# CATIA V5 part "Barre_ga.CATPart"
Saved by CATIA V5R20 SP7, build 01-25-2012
Part number: Barre_ga
Bounding box of the stored display mesh (mm): x -40 to 20, y -114.479 to 107.15, z -40 to 179.5
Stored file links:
  G:\bon\Nouveau dossier\Barre_ga.CATPart
  G:\bon\Nouveau dossier\cgirerd.CATProduct
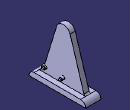
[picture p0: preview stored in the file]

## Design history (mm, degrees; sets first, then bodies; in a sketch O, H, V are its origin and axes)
Set1
  Point1 "H": linked copy from another document
  Point2 "symG": linked copy from another document
  Point3 "G": linked copy from another document
  Point4 "A": linked copy from another document
Body1 (main body)
  Sketch1 on yz-plane, origin (0, 0, 0), H (0, 1, 0), V (0, 0, 1)
    arc A1 centre (0, 152) radius 27.5 from (26.2652, 160.1479) to (-26.2652, 160.1479) ccw
    point P1 (0, 152)
    reference projected point E1 (0, 152) from Point1
    line L1 (26.2652, 160.1479) -> (82.1501, -20)
    reference projected point E2 (70.7107, 0) from Point2
    line L2 (-26.2652, 160.1479) -> (-71.9308, 12.9424)
    reference projected point E3 (-70.7107, 0) from Point3
    point P4 (82.1501, -20)
    line L3 (-82.1719, 3.5554) -> (-89.4792, -20)
    point P6 (-89.4792, -20)
    point P7 (-114.4792, -20)
    line L4 (-114.4792, -20) -> (-89.4792, -20)
    line L5 (107.1501, -20) -> (107.1501, -40)
    line L6 (107.1501, -40) -> (-114.4792, -40)
    line L7 (-114.4792, -40) -> (-114.4792, -20)
    point P8 (107.1501, -20)
    line L8 (82.1501, -20) -> (107.1501, -20)
    reference projected point E4 (-70.7107, 0) from Point3
    reference projected point E5 (0, 0) from Point4
    arc A2 centre (-70.7107, 0) radius 12 from (-72.2541, 11.9003) to (-82.1719, 3.5554) ccw
    point P11 (-70.7107, 0)
    reference projected point E6 (-70.7107, 0) from Point3
    line L9 (-71.9308, 12.9424) -> (-72.2541, 11.9003)
    radius A1 = 27.5
    distance L1 E2 = 5
    distance E3 L2 = 5
    length L5 = 20
    distance P8 P4 = 25
    distance P6 P7 = 25
    distance E4 L3 = 12
    distance L6 E5 = 40
    radius A2 = 12
    coincidence: E1 P1, L4 L8, P11 E6
    tangency: L1 A1, L2 A1
    horizontal: L4 H, L6 H, L8 H
    vertical: L5 V, L7 V
    parallelism: L3 L2, L9 L2
  Pad1: profile Sketch1, direction (-1, 0, 0), length 20
  Sketch2 on start face of Pad1, origin (0, 0, 0), H (0, 1, 0), V (0, 0, 1)
    point P1 (-114.4792, -20)
    line L1 (-114.4792, -20) -> (107.1501, -20)
    line L2 (107.1501, -20) -> (107.1501, -40)
    line L3 (107.1501, -40) -> (-114.4792, -40)
    line L4 (-114.4792, -40) -> (-114.4792, -20)
    point P2 (107.1501, -20)
    reference projected point E1 (-114.4792, -20) from vertex [face of Pad1 from Sketch1.L7 | start face of Pad1 | face of Pad1 from Sketch1.L4]
    reference projected point E2 (107.1501, -20) from vertex [face of Pad1 from Sketch1.L8 | start face of Pad1 | face of Pad1 from Sketch1.L5]
    length L4 = 20
    horizontal: L1 H, L3 H
    vertical: L2 V, L4 V
    coincidence: P1 E1, P2 E2
  Pad2: profile Sketch2, direction (1, 0, 0), length 20
  Sketch3 on end face of Pad1, origin (-20, 0, 0), H (0, -1, 0), V (0, 0, 1)
    point P1 (-107.1501, -20)
    line L1 (-107.1501, -20) -> (114.4792, -20)
    line L2 (114.4792, -20) -> (114.4792, -40)
    line L3 (114.4792, -40) -> (-107.1501, -40)
    line L4 (-107.1501, -40) -> (-107.1501, -20)
    point P2 (114.4792, -20)
    reference projected point E1 (-107.1501, -20) from vertex [face of Pad2 | end face of Pad1 | face of Pad2]
    reference projected point E2 (114.4792, -20) from vertex [face of Pad2 | end face of Pad1 | face of Pad2]
    length L2 = 20
    horizontal: L1 H, L3 H
    vertical: L2 V, L4 V
    coincidence: E1 P1, P2 E2
  Pad3: profile Sketch3, direction (-1, 0, 0), length 20
  Sketch4 on start face of Pad1, origin (0, 0, 0), H (0, 1, 0), V (0, 0, 1)
    circle A1 centre (-70.7107, 0) radius 6
    point P1 (-70.7107, 0)
    reference projected point E1 (-70.7107, 0) from Point3
    radius A1 = 6
    coincidence: P1 E1
  Pad4: profile Sketch4, direction (1, 0, 0), length 5
  Sketch5 on end face of Pad4, origin (5, 0, 0), H (0, 1, 0), V (0, 0, 1)
    circle A1 centre (-70.7107, 0) radius 4
    point P1 (-70.7107, 0)
    reference projected point E1 (-70.7107, 0) from Point3
    radius A1 = 4
    coincidence: P1 E1
  Pad5: profile Sketch5, direction (1, 0, 0), length 5
  Sketch6 on start face of Pad1, origin (0, 0, 0), H (0, 1, 0), V (0, 0, 1)
    circle A1 centre (0, 0) radius 6
    point P1 (0, 0)
    reference projected point E1 (0, 0) from Point4
    radius A1 = 6
    coincidence: P1 E1
  Pad6: profile Sketch6, direction (1, 0, 0), length 10
  Sketch7 on end face of Pad6, origin (10, 0, 0), H (0, 1, 0), V (0, 0, 1)
    circle A1 centre (0, 0) radius 4
    point P1 (0, 0)
    reference projected point E1 (0, 0) from Point4
    radius A1 = 4
    coincidence: P1 E1
  Pad7: profile Sketch7, direction (1, 0, 0), length 5
  Fillet1: radius 20, on edge [face of Pad3 | face of Pad3]
  Fillet2: radius 7, on edge [face of Pad3 | face of Pad1 from Sketch1.L1]
  Fillet3: radius 7, on edge [face of Pad1 from Sketch1.L3 | face of Pad3]
  Fillet4: radius 20, on edge [face of Pad3 | face of Pad3]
